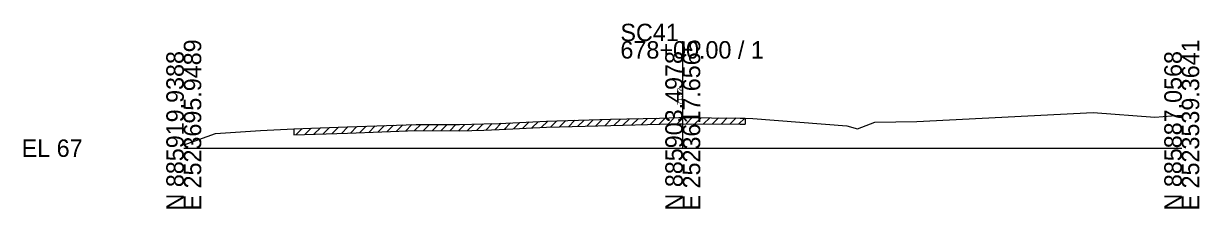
# Model space of a CAD drawing. Extents: x -26 to 183, y -10 to 24021.
# Drawn here: x -25.7 to 162.8, y 10490.3 to 10520 of the extents above; entities that cross this region are included whole.
import ezdxf

# ---------------------------------------------------------------- set-up
doc = ezdxf.new("R2010")
doc.units = 0
for name, color, linetype in [('RD_GPK_XS_Cell', 7, 'Continuous'), ('RD_XS_ExGround', 7, 'Continuous'), ('RD_XS_ExPaveRet', 7, 'Continuous'), ('RD_XS_TX_Elev_EX', 7, 'Continuous')]:
    doc.layers.add(name, color=color, linetype=linetype)

msp = doc.modelspace()

# ---------------------------------------------------------------- linework, layer by layer
at = {"layer": 'RD_GPK_XS_Cell'}
for p, q in [((80, 10500), (80, 10517.2)), ((0, 10500), (80, 10500)), ((80, 10500), (160, 10500))]:
    msp.add_line(p, q, dxfattribs=at)
at = {"layer": 'RD_XS_ExGround'}
for p, q in [((117.5, 10504.28), (145.82, 10505.73)), ((145.82, 10505.73), (155.67, 10504.99)), ((155.67, 10504.99), (158.38, 10505.22)), ((158.38, 10505.22), (160, 10505.32)), ((17.67, 10503.13), (26.22, 10503.42)), ((26.22, 10503.42), (37.25, 10503.83)), ((37.25, 10503.83), (44.22, 10503.79)), ((44.22, 10503.79), (48.09, 10503.9)), ((48.09, 10503.9), (50.54, 10503.98)), ((50.54, 10503.98), (58.13, 10504.37)), ((58.13, 10504.37), (68.41, 10504.65)), ((68.41, 10504.65), (76.29, 10504.85)), ((76.29, 10504.85), (79.35, 10504.93)), ((79.35, 10504.93), (80, 10504.92)), ((80, 10504.92), (89.22, 10504.85)), ((89.22, 10504.85), (90.02, 10504.85)), ((90.02, 10504.85), (91.24, 10504.75)), ((91.24, 10504.75), (106.31, 10503.61)), ((106.31, 10503.61), (107.99, 10503.09)), ((107.99, 10503.09), (110.77, 10504.16)), ((110.77, 10504.16), (117.5, 10504.28)), ((0.51, 10500.7), (5.06, 10502.34)), ((5.06, 10502.34), (12.32, 10502.87)), ((12.32, 10502.87), (17.67, 10503.13)), ((0, 10500.52), (0.51, 10500.7))]:
    msp.add_line(p, q, dxfattribs=at)
at = {"layer": 'RD_XS_ExPaveRet'}
for p, q in [((17.94, 10502.14), (18.97, 10503.17)), ((19.4, 10502.19), (20.44, 10503.22)), ((20.87, 10502.24), (21.9, 10503.27)), ((22.33, 10502.29), (23.37, 10503.32)), ((23.79, 10502.34), (24.83, 10503.37)), ((25.26, 10502.39), (26.29, 10503.42)), ((26.72, 10502.44), (27.76, 10503.48)), ((28.19, 10502.49), (29.23, 10503.53)), ((29.66, 10502.55), (30.7, 10503.59)), ((31.13, 10502.6), (32.17, 10503.64)), ((32.6, 10502.66), (33.64, 10503.69)), ((34.07, 10502.71), (35.11, 10503.75)), ((35.54, 10502.76), (36.57, 10503.8)), ((37, 10502.82), (38.01, 10503.82)), ((38.42, 10502.82), (39.41, 10503.82)), ((39.83, 10502.81), (40.82, 10503.81)), ((41.23, 10502.8), (42.23, 10503.8)), ((42.64, 10502.8), (43.63, 10503.79)), ((44.04, 10502.79), (45.07, 10503.81)), ((45.49, 10502.82), (46.53, 10503.86)), ((46.95, 10502.87), (47.98, 10503.9)), ((48.41, 10502.91), (49.44, 10503.95)), ((49.87, 10502.96), (50.91, 10504)), ((50.58, 10502.98), (58.17, 10503.37)), ((51.35, 10503.02), (52.4, 10504.08)), ((52.84, 10503.1), (53.89, 10504.15)), ((54.33, 10503.17), (55.38, 10504.23)), ((55.82, 10503.25), (56.87, 10504.3)), ((57.31, 10503.32), (58.36, 10504.37)), ((58.17, 10503.37), (68.44, 10503.65)), ((58.78, 10503.38), (59.81, 10504.41)), ((60.24, 10503.42), (61.26, 10504.45)), ((61.69, 10503.46), (62.72, 10504.49)), ((63.14, 10503.5), (64.17, 10504.53)), ((64.6, 10503.54), (65.63, 10504.57)), ((66.05, 10503.58), (67.08, 10504.61)), ((67.51, 10503.62), (68.53, 10504.65)), ((68.44, 10503.65), (76.31, 10503.85)), ((68.96, 10503.66), (69.99, 10504.69)), ((70.41, 10503.7), (71.44, 10504.72)), ((71.86, 10503.73), (72.89, 10504.76)), ((73.31, 10503.77), (74.34, 10504.8)), ((74.76, 10503.81), (75.79, 10504.83)), ((76.21, 10503.84), (77.24, 10504.87)), ((76.31, 10503.85), (79.36, 10503.93)), ((77.67, 10503.88), (78.69, 10504.91)), ((79.12, 10503.92), (80.12, 10504.92)), ((79.36, 10503.93), (79.99, 10503.92)), ((79.99, 10503.92), (89.21, 10503.85)), ((80.53, 10503.92), (81.52, 10504.91)), ((81.93, 10503.91), (82.93, 10504.9)), ((83.34, 10503.9), (84.33, 10504.89)), ((84.74, 10503.89), (85.73, 10504.88)), ((86.14, 10503.88), (87.14, 10504.87)), ((87.55, 10503.87), (88.54, 10504.86)), ((88.95, 10503.85), (89.94, 10504.85)), ((89.21, 10503.85), (90.02, 10503.85)), ((17.67, 10502.13), (26.26, 10502.42)), ((26.26, 10502.42), (37.27, 10502.83)), ((37.27, 10502.83), (44.24, 10502.79)), ((44.24, 10502.79), (48.13, 10502.9)), ((48.13, 10502.9), (50.58, 10502.98))]:
    msp.add_line(p, q, dxfattribs=at)
for points in [[(90.02, 10504.85), (90.02, 10503.85)], [(17.67, 10503.13), (17.67, 10502.13)]]:
    msp.add_lwpolyline(points, dxfattribs=at)

# ---------------------------------------------------------------- texts
at = {"layer": 'RD_GPK_XS_Cell'}
for s, p in [('SC41', (70, 10517.2)), ('678+00.00 / 1', (70, 10514.4)), ('EL 67', (-26, 10498.6))]:
    msp.add_text(s, height=2.8, dxfattribs=at).set_placement(p)
for s, p in [('E 2523695.9489', (2.8, 10490)), ('E 2523617.6565', (82.8, 10490)), ('E 2523539.3641', (162.8, 10490)), ('N 885919.9388', (0, 10490)), ('N 885903.4978', (80, 10490)), ('N 885887.0568', (160, 10490))]:
    msp.add_text(s, height=2.8, rotation=90, dxfattribs=at).set_placement(p)
at = {"layer": 'RD_XS_TX_Elev_EX'}
msp.add_text('71.92', height=0.8, rotation=90, dxfattribs=at).set_placement((79.9, 10506.92))

doc.saveas('drawing.dxf')
